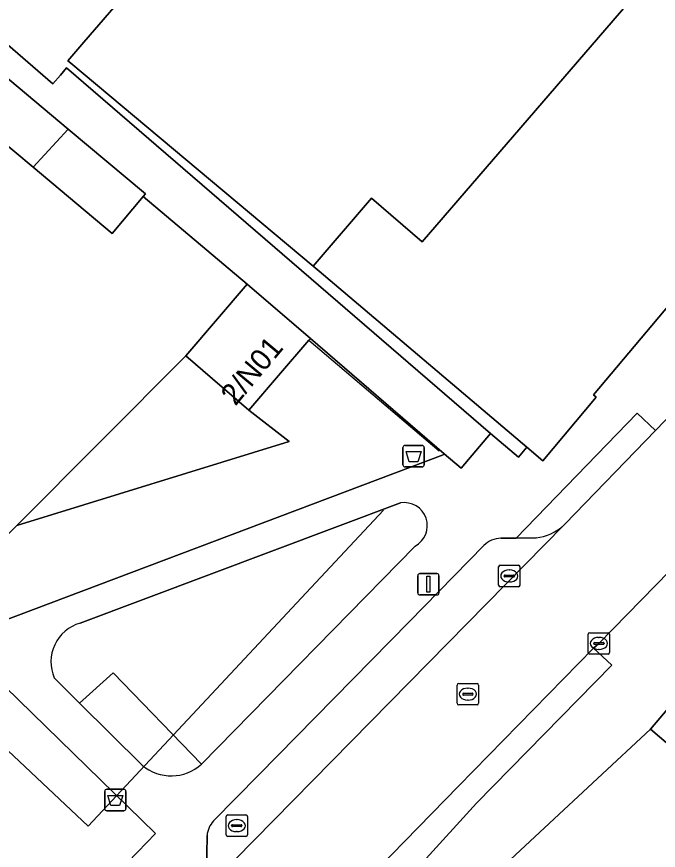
# Model space of a CAD drawing. Extents: x 162344 to 162869, y 381217 to 381818.
# Drawn here: x 162638.72 to 162668.66, y 381626.94 to 381665.84 of the extents above; entities that cross this region are included whole.
import ezdxf

# ---------------------------------------------------------------- set-up
doc = ezdxf.new("R2010")
doc.units = 0
for name, color, linetype in [('IMGEO_Afvalbak', 7, 'Continuous'), ('IMGEO_Erf', 7, 'Continuous'), ('IMGEO_Groenvoorziening', 7, 'Continuous'), ('IMGEO_Hek', 7, 'Continuous'), ('IMGEO_Kolk', 7, 'Continuous'), ('IMGEO_Lichtmast', 7, 'Continuous'), ('IMGEO_Pand', 7, 'Continuous'), ('IMGEO_Pand_nummerreeks', 7, 'Continuous'), ('IMGEO_Parkeervlak_open', 7, 'Continuous'), ('IMGEO_Rijbaan_lokaal_open', 7, 'Continuous'), ('IMGEO_Rioolput', 7, 'Continuous'), ('IMGEO_Voetpad_open', 7, 'Continuous')]:
    doc.layers.add(name, color=color, linetype=linetype)

msp = doc.modelspace()

# ---------------------------------------------------------------- linework, layer by layer
at = {"layer": 'IMGEO_Afvalbak'}
for p, q in [((162656.75, 381644.93), (162656.75, 381645.73)), ((162656.75, 381645.73), (162656.75, 381644.93)), ((162656.85, 381645.83), (162657.64, 381645.83)), ((162657.64, 381645.83), (162656.85, 381645.83)), ((162657.74, 381645.73), (162657.74, 381644.93)), ((162657.74, 381644.93), (162657.74, 381645.73)), ((162657.64, 381644.83), (162656.85, 381644.83)), ((162656.85, 381644.83), (162657.64, 381644.83)), ((162642.832, 381628.889), (162642.832, 381629.689)), ((162642.832, 381629.689), (162642.832, 381628.889)), ((162642.932, 381629.789), (162643.722, 381629.789)), ((162643.722, 381629.789), (162642.932, 381629.789)), ((162643.822, 381629.689), (162643.822, 381628.889)), ((162643.822, 381628.889), (162643.822, 381629.689)), ((162643.722, 381628.789), (162642.932, 381628.789)), ((162642.932, 381628.789), (162643.722, 381628.789))]:
    msp.add_line(p, q, dxfattribs=at)
for points in [[(162656.893, 381645.544), (162657.597, 381645.544), (162657.448, 381645.074), (162657.042, 381645.074), (162656.893, 381645.544)], [(162642.975, 381629.503), (162643.679, 381629.503), (162643.53, 381629.033), (162643.124, 381629.033), (162642.975, 381629.503)]]:
    msp.add_lwpolyline(points, dxfattribs=at)
for centre, start, end in [((162656.85, 381645.73), 90, 180), ((162656.85, 381645.73), 90, 180), ((162657.64, 381645.73), 0, 90), ((162657.64, 381645.73), 360, 90), ((162656.85, 381644.93), 180, 270), ((162656.85, 381644.93), 180, 270), ((162657.64, 381644.93), 270, 0), ((162657.64, 381644.93), 270, 0), ((162642.932, 381629.689), 90, 180), ((162642.932, 381629.689), 90, 180), ((162643.722, 381629.689), 0, 90), ((162643.722, 381629.689), 360, 90), ((162642.932, 381628.889), 180, 270), ((162642.932, 381628.889), 180, 270), ((162643.722, 381628.889), 270, 0), ((162643.722, 381628.889), 270, 0)]:
    msp.add_arc(centre, 0.1, start, end, dxfattribs=at)
at = {"layer": 'IMGEO_Erf'}
for points in [[(162636.428, 381666.14), (162640.413, 381662.701), (162640.768, 381663.113), (162641.053, 381663.444), (162660.838, 381646.394), (162662.142, 381645.292), (162662.532, 381645.744), (162652.841, 381653.967), (162652.558, 381654.203), (162641.244, 381663.665), (162641.107, 381663.78), (162641.857, 381664.649), (162644.958, 381668.241), (162644.725, 381668.442), (162640.323, 381672.242), (162642.842, 381675.159), (162644.71, 381677.345), (162648.449, 381681.676), (162649.606, 381683.017), (162652.873, 381686.801), (162650.823, 381688.494), (162651.895, 381689.662), (162641.109, 381699.217), (162608.637, 381727.011)], [(162637.13, 381640.474), (162638.739, 381642.093), (162646.61, 381650.012), (162649.475, 381653.355), (162644.628, 381657.449), (162643.187, 381655.726), (162639.487, 381658.819), (162636.064, 381661.68)]]:
    msp.add_lwpolyline(points, dxfattribs=at)
at = {"layer": 'IMGEO_Groenvoorziening'}
for points in [[(162658.632, 381645.394), (162658.671, 381645.439), (162652.429, 381650.823), (162652.358, 381650.739), (162650.946, 381649.092), (162649.564, 381647.48), (162651.445, 381646.012), (162638.739, 381642.093), (162637.13, 381640.474), (162633.056, 381636.194), (162633.394, 381635.882)], [(162649.564, 381647.48), (162646.61, 381650.012), (162638.739, 381642.093), (162651.445, 381646.012)]]:
    msp.add_lwpolyline(points, close=True, dxfattribs=at)
for points in [[(162656.632, 381643.15), (162641.683, 381637.54)], [(162640.478, 381634.982), (162641.661, 381633.808), (162643.234, 381635.23), (162647.35, 381630.961), (162657.312, 381641.139)], [(162641.025, 381623.407), (162644.357, 381626.848), (162645.202, 381627.721), (162637.524, 381635.211)], [(162643.234, 381635.23), (162641.661, 381633.808), (162644.579, 381630.912)], [(162647.35, 381630.961), (162643.234, 381635.23)]]:
    msp.add_lwpolyline(points, dxfattribs=at)
for centre, radius, start, end in [((162656.811, 381642.09), 1.075, 297.7963, 99.5687), ((162642.199, 381635.734), 1.878, 105.9476, 203.6049), ((162645.937, 381632.513), 2.099, 229.6987, 312.3274)]:
    msp.add_arc(centre, radius, start, end, dxfattribs=at)
at = {"layer": 'IMGEO_Hek'}
for points in [[(162652.358, 381650.739), (162658.431, 381645.579)], [(162655.842, 381642.815), (162652.232, 381638.954)], [(162652.232, 381638.954), (162642.062, 381628.072), (162636.69, 381633.102)]]:
    msp.add_lwpolyline(points, dxfattribs=at)
at = {"layer": 'IMGEO_Kolk'}
for p, q in [((162661.209, 381639.316), (162661.209, 381640.168)), ((162661.284, 381640.242), (162662.136, 381640.242)), ((162662.21, 381640.168), (162662.21, 381639.316)), ((162661.468, 381639.736), (162661.468, 381639.748)), ((162661.511, 381639.785), (162661.909, 381639.785)), ((162661.697, 381640.022), (162661.722, 381640.022)), ((162661.952, 381639.748), (162661.952, 381639.736)), ((162661.906, 381639.699), (162661.508, 381639.699)), ((162661.72, 381639.462), (162661.695, 381639.462)), ((162662.136, 381639.242), (162661.284, 381639.242)), ((162665.465, 381637.095), (162666.317, 381637.095)), ((162665.39, 381636.169), (162665.39, 381637.021)), ((162665.692, 381636.638), (162666.09, 381636.638)), ((162665.878, 381636.875), (162665.903, 381636.875)), ((162666.391, 381637.021), (162666.391, 381636.169)), ((162665.649, 381636.589), (162665.649, 381636.601)), ((162666.087, 381636.552), (162665.689, 381636.552)), ((162665.901, 381636.315), (162665.876, 381636.315)), ((162666.133, 381636.601), (162666.133, 381636.589)), ((162666.317, 381636.095), (162665.465, 381636.095)), ((162648.495, 381627.666), (162648.495, 381628.518)), ((162648.57, 381628.592), (162649.422, 381628.592)), ((162649.496, 381628.518), (162649.496, 381627.666)), ((162648.754, 381628.086), (162648.754, 381628.098)), ((162648.797, 381628.135), (162649.195, 381628.135)), ((162648.983, 381628.372), (162649.008, 381628.372)), ((162649.238, 381628.098), (162649.238, 381628.086)), ((162649.192, 381628.049), (162648.794, 381628.049)), ((162649.006, 381627.812), (162648.981, 381627.812)), ((162649.422, 381627.592), (162648.57, 381627.592))]:
    msp.add_line(p, q, dxfattribs=at)
for points in [[(162661.209, 381639.316), (162661.209, 381640.168)], [(162661.284, 381640.242), (162662.136, 381640.242)], [(162662.21, 381640.168), (162662.21, 381639.316)], [(162662.136, 381639.242), (162661.284, 381639.242)], [(162665.465, 381637.095), (162666.317, 381637.095)], [(162665.39, 381636.169), (162665.39, 381637.021)], [(162666.391, 381637.021), (162666.391, 381636.169)], [(162666.317, 381636.095), (162665.465, 381636.095)], [(162648.495, 381627.666), (162648.495, 381628.518)], [(162648.57, 381628.592), (162649.422, 381628.592)], [(162649.496, 381628.518), (162649.496, 381627.666)], [(162649.422, 381627.592), (162648.57, 381627.592)]]:
    msp.add_lwpolyline(points, dxfattribs=at)
for centre, radius, start, end in [((162661.286, 381640.166), 0.0765, 91.552, 178.448), ((162661.286, 381640.166), 0.0765, 91.552, 178.448), ((162662.134, 381640.166), 0.0765, 1.552, 88.448), ((162662.134, 381640.166), 0.0765, 1.552, 88.448), ((162661.508, 381639.745), 0.0403, 85.8775, 175.7526), ((162661.913, 381639.747), 0.0386, 1.7309, 96.639), ((162661.505, 381639.735), 0.0366, 178.938, 274.7102), ((162661.909, 381639.742), 0.043, 264.8664, 352.4533), ((162661.286, 381639.318), 0.0765, 181.552, 268.448), ((162661.286, 381639.318), 0.0765, 181.552, 268.448), ((162662.134, 381639.318), 0.0765, 271.552, 358.448), ((162662.134, 381639.318), 0.0765, 271.552, 358.448), ((162665.467, 381637.019), 0.0765, 91.552, 178.448), ((162665.467, 381637.019), 0.0765, 91.552, 178.448), ((162666.315, 381637.019), 0.0765, 1.552, 88.448), ((162666.315, 381637.019), 0.0765, 1.552, 88.448), ((162665.689, 381636.598), 0.0403, 85.8775, 175.7526), ((162666.094, 381636.6), 0.0386, 1.7309, 96.639), ((162665.686, 381636.588), 0.0366, 178.938, 274.7102), ((162666.09, 381636.595), 0.043, 264.8664, 352.4533), ((162665.467, 381636.171), 0.0765, 181.552, 268.448), ((162665.467, 381636.171), 0.0765, 181.552, 268.448), ((162666.315, 381636.171), 0.0765, 271.552, 358.448), ((162666.315, 381636.171), 0.0765, 271.552, 358.448), ((162648.572, 381628.516), 0.0765, 91.552, 178.448), ((162648.572, 381628.516), 0.0765, 91.552, 178.448), ((162649.42, 381628.516), 0.0765, 1.552, 88.448), ((162649.42, 381628.516), 0.0765, 1.552, 88.448), ((162648.794, 381628.095), 0.0403, 85.8775, 175.7526), ((162648.791, 381628.085), 0.0366, 178.938, 274.7102), ((162649.195, 381628.092), 0.043, 264.8664, 352.4533), ((162649.199, 381628.097), 0.0386, 1.7309, 96.639), ((162648.572, 381627.668), 0.0765, 181.552, 268.448), ((162648.572, 381627.668), 0.0765, 181.552, 268.448), ((162649.42, 381627.668), 0.0765, 271.552, 358.448), ((162649.42, 381627.668), 0.0765, 271.552, 358.448)]:
    msp.add_arc(centre, radius, start, end, dxfattribs=at)
for centre, major_axis, ratio, start_param, end_param in [((162661.696, 381639.742), (-0.387, 0.002), 0.722429, 4.712389, 7.853982), ((162661.721, 381639.742), (-0.39, 0.002), 0.717154, 1.570796, 4.712389), ((162665.877, 381636.595), (-0.387, 0.002), 0.722429, 4.712389, 7.853982), ((162665.902, 381636.595), (-0.39, 0.002), 0.717154, 1.570796, 4.712389), ((162648.982, 381628.092), (-0.387, 0.002), 0.722429, 4.712389, 7.853982), ((162649.007, 381628.092), (-0.39, 0.002), 0.717154, 1.570796, 4.712389)]:
    msp.add_ellipse(centre, major_axis=major_axis, ratio=ratio, start_param=start_param, end_param=end_param, dxfattribs=at)
at = {"layer": 'IMGEO_Lichtmast'}
for p, q in [((162657.44, 381638.955), (162657.44, 381639.755)), ((162657.44, 381639.755), (162657.44, 381638.955)), ((162657.54, 381639.855), (162658.33, 381639.855)), ((162658.33, 381639.855), (162657.54, 381639.855)), ((162658.43, 381639.755), (162658.43, 381638.955)), ((162658.43, 381638.955), (162658.43, 381639.755)), ((162658.33, 381638.855), (162657.54, 381638.855)), ((162657.54, 381638.855), (162658.33, 381638.855))]:
    msp.add_line(p, q, dxfattribs=at)
msp.add_lwpolyline([(162657.86, 381639.73), (162658.01, 381639.73), (162658.01, 381638.98), (162657.86, 381638.98), (162657.86, 381639.73)], dxfattribs=at)
for centre, start, end in [((162657.54, 381639.755), 90, 180), ((162657.54, 381639.755), 90, 180), ((162658.33, 381639.755), 0, 90), ((162658.33, 381639.755), 360, 90), ((162657.54, 381638.955), 180, 270), ((162657.54, 381638.955), 180, 270), ((162658.33, 381638.955), 270, 0), ((162658.33, 381638.955), 270, 0)]:
    msp.add_arc(centre, 0.1, start, end, dxfattribs=at)
at = {"layer": 'IMGEO_Pand'}
for points in [[(162671.169, 381671.008), (162670.832, 381671.299), (162657.765, 381682.579), (162657.285, 381682.992), (162644.725, 381668.442), (162644.958, 381668.241), (162641.857, 381664.649), (162641.107, 381663.78), (162641.244, 381663.665), (162652.558, 381654.203), (162655.287, 381657.365), (162657.64, 381655.334)], [(162679.213, 381664.065), (162671.169, 381671.008), (162657.64, 381655.334), (162655.287, 381657.365), (162652.558, 381654.203), (162652.841, 381653.967), (162662.532, 381645.744), (162663.268, 381645.119), (162665.772, 381648.078), (162665.642, 381648.188), (162671.986, 381655.736), (162672.34, 381656.157), (162672.478, 381656.041), (162678.918, 381663.694)], [(162637.535, 381663.439), (162636.064, 381661.68), (162639.487, 381658.819), (162641.133, 381660.582), (162637.609, 381663.528)], [(162641.133, 381660.582), (162639.487, 381658.819), (162643.187, 381655.726), (162644.628, 381657.449), (162644.732, 381657.574)], [(162650.946, 381649.092), (162652.358, 381650.739), (162652.429, 381650.823), (162649.475, 381653.355), (162646.61, 381650.012), (162649.564, 381647.48)], [(162708.391, 381636.674), (162702.596, 381641.595), (162701.664, 381641.32), (162701.463, 381641.084), (162699.87, 381642.371), (162700.101, 381642.634), (162700.183, 381643.545), (162694.188, 381648.719), (162682.884, 381635.503), (162675.845, 381641.49), (162668.299, 381632.588), (162683.248, 381619.871), (162690.819, 381628.753), (162692.852, 381627.024), (162697.07, 381623.436)]]:
    msp.add_lwpolyline(points, close=True, dxfattribs=at)
at = {"layer": 'IMGEO_Parkeervlak_open'}
for points in [[(162647.112, 381624.677), (162664.256, 381642.113)], [(162662.958, 381641.516), (162662.03, 381641.507), (162661.309, 381641.5)], [(162660.527, 381641.166), (162657.042, 381637.598), (162650.017, 381630.457), (162647.913, 381628.318)], [(162647.608, 381627.63), (162647.576, 381625.886)]]:
    msp.add_lwpolyline(points, dxfattribs=at)
for centre, radius, start, end in [((162662.669, 381643.853), 2.355, 277.0405, 312.3585), ((162661.349, 381640.323), 1.177, 91.9598, 134.2958), ((162648.769, 381627.527), 1.166, 137.259, 174.9242)]:
    msp.add_arc(centre, radius, start, end, dxfattribs=at)
at = {"layer": 'IMGEO_Rijbaan_lokaal_open'}
for points in [[(162675.14, 381646.068), (162675.203, 381646.144), (162684.096, 381656.787), (162685.234, 381658.098), (162685.311, 381658.19), (162681.539, 381661.361), (162681.453, 381661.251), (162679.069, 381658.505), (162671.388, 381649.497), (162670.68, 381648.753), (162668.538, 381646.537), (162664.319, 381642.173), (162664.256, 381642.113), (162647.112, 381624.677), (162650.694, 381621.134), (162651.603, 381622.055), (162651.745, 381622.229), (162653.055, 381623.522), (162653.298, 381623.761), (162654.062, 381624.523), (162654.327, 381624.795), (162659.336, 381629.932), (162665.637, 381636.368), (162665.891, 381636.595)], [(162709.112, 381599.269), (162713.008, 381603.857), (162689.779, 381623.657), (162692.852, 381627.024), (162690.819, 381628.753), (162683.248, 381619.871), (162668.299, 381632.588), (162663.359, 381627.992), (162660.865, 381625.672), (162701.58, 381592.223), (162702.588, 381593.261), (162703.602, 381592.22), (162705.867, 381594.879), (162705.586, 381595.117), (162706.321, 381595.982), (162684.762, 381614.058), (162687.533, 381617.362)]]:
    msp.add_lwpolyline(points, close=True, dxfattribs=at)
at = {"layer": 'IMGEO_Rioolput'}
for p, q in [((162659.352, 381634.728), (162660.204, 381634.728)), ((162659.277, 381633.802), (162659.277, 381634.654)), ((162659.765, 381634.508), (162659.79, 381634.508)), ((162660.278, 381634.654), (162660.278, 381633.802)), ((162659.536, 381634.222), (162659.536, 381634.234)), ((162659.974, 381634.185), (162659.576, 381634.185)), ((162659.579, 381634.271), (162659.977, 381634.271)), ((162659.788, 381633.948), (162659.763, 381633.948)), ((162660.02, 381634.234), (162660.02, 381634.222)), ((162660.204, 381633.728), (162659.352, 381633.728))]:
    msp.add_line(p, q, dxfattribs=at)
for points in [[(162659.352, 381634.728), (162660.204, 381634.728)], [(162659.277, 381633.802), (162659.277, 381634.654)], [(162660.278, 381634.654), (162660.278, 381633.802)], [(162660.204, 381633.728), (162659.352, 381633.728)]]:
    msp.add_lwpolyline(points, dxfattribs=at)
for centre, radius, start, end in [((162659.354, 381634.652), 0.0765, 91.552, 178.448), ((162659.354, 381634.652), 0.0765, 91.552, 178.448), ((162660.202, 381634.652), 0.0765, 1.552, 88.448), ((162660.202, 381634.652), 0.0765, 1.552, 88.448), ((162659.576, 381634.231), 0.0403, 85.8775, 175.7526), ((162659.573, 381634.221), 0.0366, 178.938, 274.7102), ((162659.977, 381634.228), 0.043, 264.8664, 352.4533), ((162659.981, 381634.233), 0.0386, 1.7309, 96.639), ((162659.354, 381633.804), 0.0765, 181.552, 268.448), ((162659.354, 381633.804), 0.0765, 181.552, 268.448), ((162660.202, 381633.804), 0.0765, 271.552, 358.448), ((162660.202, 381633.804), 0.0765, 271.552, 358.448)]:
    msp.add_arc(centre, radius, start, end, dxfattribs=at)
for centre, major_axis, ratio, start_param, end_param in [((162659.764, 381634.228), (-0.387, 0.002), 0.722429, 4.712389, 7.853982), ((162659.789, 381634.228), (-0.39, 0.002), 0.717154, 1.570796, 4.712389)]:
    msp.add_ellipse(centre, major_axis=major_axis, ratio=ratio, start_param=start_param, end_param=end_param, dxfattribs=at)
at = {"layer": 'IMGEO_Voetpad_open'}
for points in [[(162637.609, 381663.528), (162641.133, 381660.582), (162644.732, 381657.574), (162644.628, 381657.449), (162649.475, 381653.355), (162652.429, 381650.823), (162658.671, 381645.439), (162659.465, 381644.774), (162660.838, 381646.394), (162641.053, 381663.444), (162640.768, 381663.113), (162640.413, 381662.701), (162636.428, 381666.14)], [(162681.453, 381661.251), (162681.539, 381661.361), (162679.213, 381664.065), (162678.918, 381663.694), (162672.478, 381656.041), (162672.34, 381656.157), (162671.986, 381655.736), (162665.642, 381648.188), (162665.772, 381648.078), (162663.268, 381645.119), (162662.532, 381645.744), (162662.142, 381645.292), (162660.838, 381646.394), (162659.465, 381644.774), (162658.671, 381645.439), (162658.632, 381645.394), (162633.394, 381635.882), (162631.144, 381634.866), (162631.862, 381634.714)], [(162667.683, 381647.337), (162668.538, 381646.537), (162670.68, 381648.753)], [(162661.309, 381641.5), (162662.03, 381641.507), (162667.683, 381647.337)], [(162668.538, 381646.537), (162667.683, 381647.337), (162662.03, 381641.507), (162662.958, 381641.516)], [(162664.256, 381642.113), (162664.319, 381642.173), (162668.538, 381646.537)], [(162675.203, 381646.144), (162675.14, 381646.068), (162665.891, 381636.595), (162665.637, 381636.368), (162666.501, 381635.573), (162660.187, 381629.138), (162655.332, 381623.81), (162654.327, 381624.795), (162654.062, 381624.523), (162653.298, 381623.761), (162653.055, 381623.522), (162654.468, 381622.12), (162651.186, 381618.784), (162648.124, 381615.672)], [(162641.683, 381637.54), (162656.632, 381643.15)], [(162588.284, 381559.145), (162591.596, 381561.939), (162592.32, 381562.545), (162599.456, 381568.935), (162599.604, 381568.769), (162617.236, 381583.812), (162622.507, 381588.51), (162623.179, 381589.147), (162630.312, 381595.808), (162647.237, 381612.021), (162652.285, 381616.955), (162652.976, 381617.664), (162659.686, 381624.575), (162660.865, 381625.672), (162663.359, 381627.992), (162668.299, 381632.588), (162675.845, 381641.49)], [(162657.312, 381641.139), (162647.35, 381630.961)], [(162647.913, 381628.318), (162650.017, 381630.457), (162657.042, 381637.598), (162660.527, 381641.166)], [(162637.524, 381635.211), (162645.202, 381627.721), (162644.357, 381626.848), (162641.025, 381623.407)], [(162644.579, 381630.912), (162641.661, 381633.808), (162640.478, 381634.982)], [(162647.576, 381625.886), (162647.608, 381627.63)]]:
    msp.add_lwpolyline(points, dxfattribs=at)
msp.add_lwpolyline([(162665.637, 381636.368), (162659.336, 381629.932), (162654.327, 381624.795), (162655.332, 381623.81), (162660.187, 381629.138), (162666.501, 381635.573)], close=True, dxfattribs=at)
for centre, radius, start, end in [((162656.811, 381642.09), 1.075, 297.7963, 99.5687), ((162662.669, 381643.853), 2.355, 277.0405, 312.3585), ((162661.349, 381640.323), 1.177, 91.9598, 134.2958), ((162642.199, 381635.734), 1.878, 105.9476, 203.6049), ((162645.937, 381632.513), 2.099, 229.6987, 312.3274), ((162648.769, 381627.527), 1.166, 137.259, 174.9242)]:
    msp.add_arc(centre, radius, start, end, dxfattribs=at)

# ---------------------------------------------------------------- texts
at = {"layer": 'IMGEO_Pand_nummerreeks'}
msp.add_text('2/N01', height=1, rotation=50.1479, dxfattribs=at).set_placement((162648.93, 381647.636))

doc.saveas('drawing.dxf')
